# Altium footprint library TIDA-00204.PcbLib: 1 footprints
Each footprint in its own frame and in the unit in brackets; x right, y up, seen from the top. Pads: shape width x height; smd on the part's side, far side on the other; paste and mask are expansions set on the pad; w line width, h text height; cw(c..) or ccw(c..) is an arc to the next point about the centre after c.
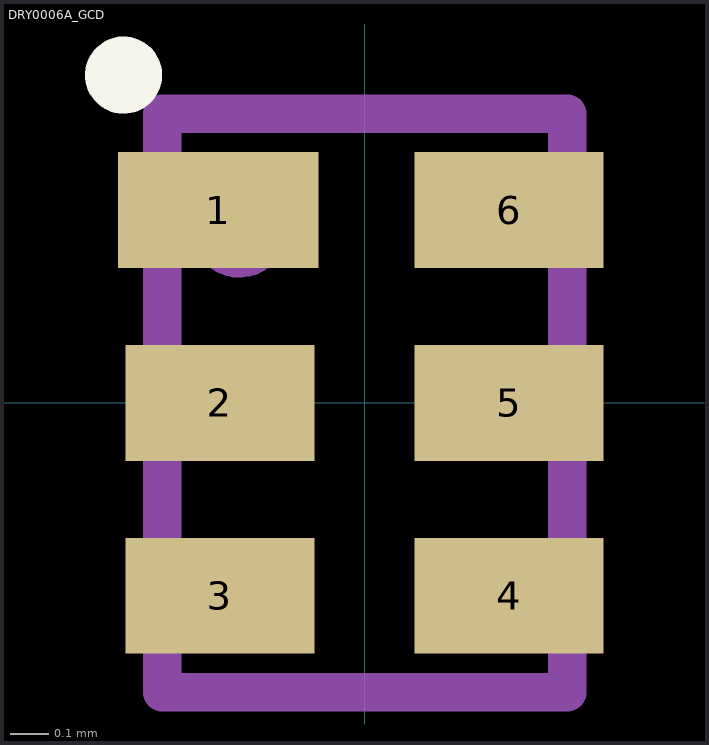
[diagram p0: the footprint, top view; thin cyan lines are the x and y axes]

## DRY0006A_GCD [mm] "PSON, 6-Leads, Body 1x1.45mm, Pitch 0.5mm, TI Recommended"
height 0.6
pads (6):
  rect 0.52x0.3 smd mask+0.05: 1(-0.38,0.5)
  rect 0.49x0.3 smd: 2(-0.375,0) 3(-0.375,-0.5) 4(0.375,-0.5) 5(0.375,0) 6(0.375,0.5)
Top Overlay:
  circle w0.1: c-0.625,0.85 r0.05
M5 Assembly Top:
  circle w0.05: c-0.325,0.45 r0.1
  lines w0.1: -0.525,-0.75 -0.525,0.75 0.525,0.75 0.525,-0.75 -0.525,-0.75
  text ".Designator" at -0.075,0.575 h0.3
3D body: height 0.6, standoff 0, extent -0.525,-0.75 0.525,0.75
3D body: height 0.61, standoff 0.3, extent -0.433,0.342 -0.217,0.558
